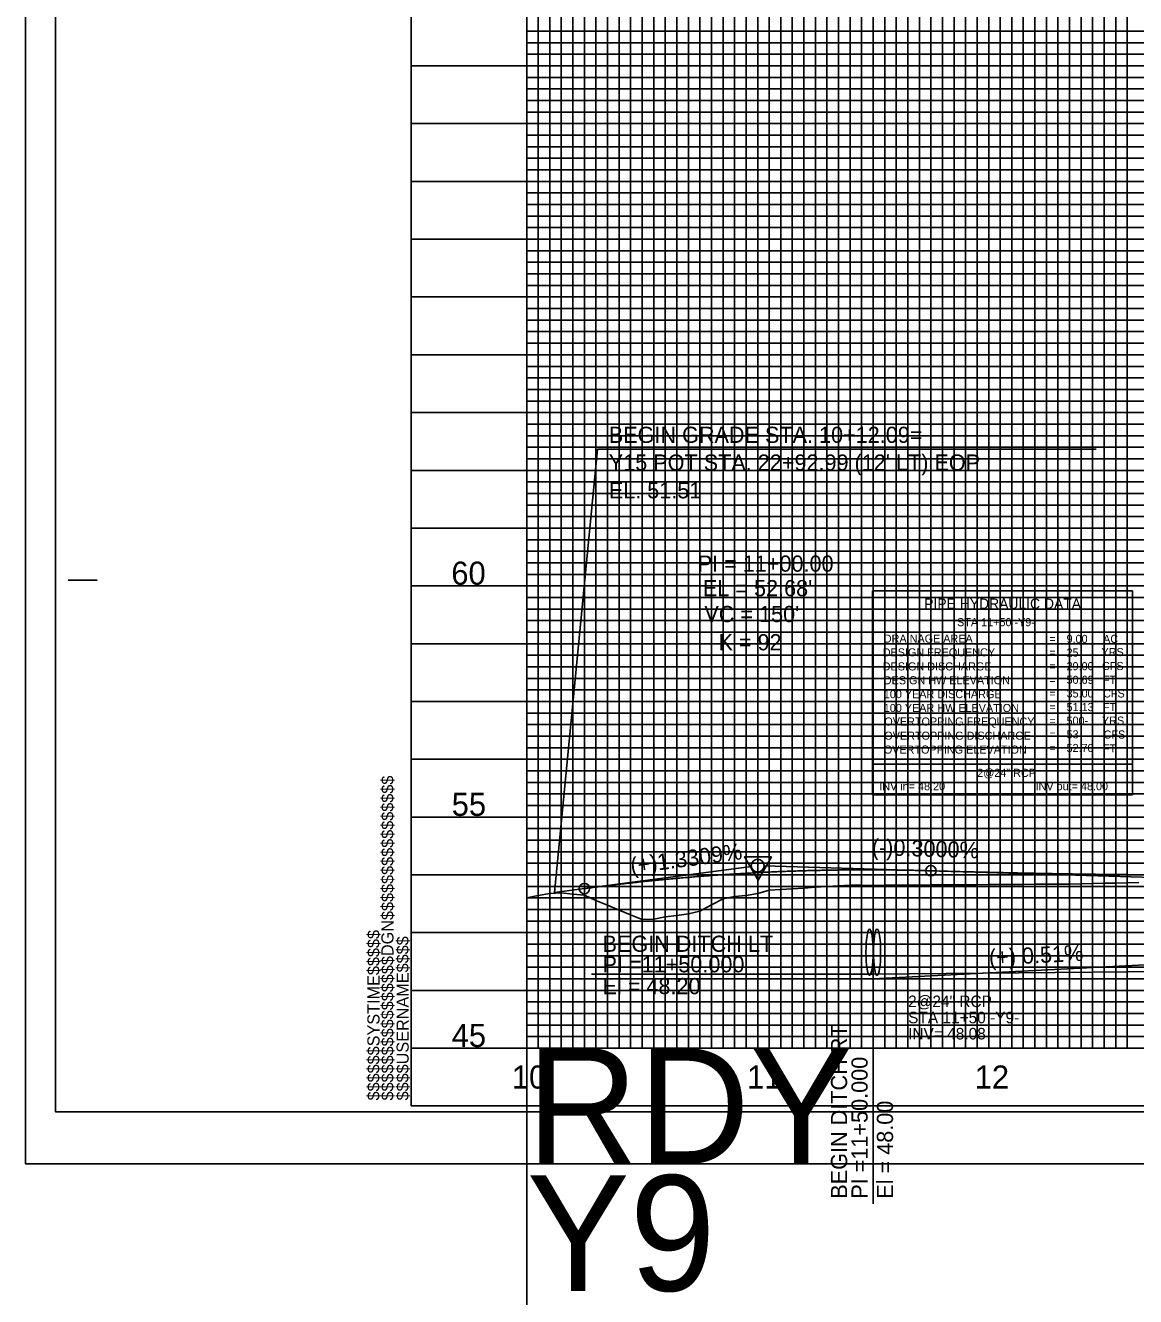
# Model space of a CAD drawing. Extents: x 2345490 to 2436403, y 465165 to 573888.
# Drawn here: x 2381463 to 2381944, y 536093 to 536643 of the extents above; entities that cross this region are included whole.
import ezdxf

# ---------------------------------------------------------------- set-up
doc = ezdxf.new("R2010")
doc.units = 0
for name, color, linetype in [('Old_Level_1', 7, 'Continuous'), ('Old_Level_18', 7, 'Continuous'), ('Old_Level_2', 7, 'Continuous'), ('Old_Level_3', 7, 'Continuous'), ('Old_Level_4', 7, 'Continuous'), ('Old_Level_40', 7, 'Continuous'), ('Old_Level_41', 7, 'Continuous'), ('Old_Level_42', 7, 'Continuous'), ('Old_Level_43', 7, 'Continuous'), ('Old_Level_50', 7, 'Continuous'), ('Old_Level_51', 7, 'Continuous'), ('Old_Level_52', 7, 'Continuous'), ('Old_Level_57', 7, 'Continuous'), ('Old_Level_62', 7, 'Continuous'), ('Old_Level_63', 7, 'Continuous')]:
    doc.layers.add(name, color=color, linetype=linetype)

msp = doc.modelspace()

# ---------------------------------------------------------------- linework, layer by layer
at = {"layer": 'Old_Level_1'}
msp.add_lwpolyline([(2381680.454, 536265.78575), (2381685.454, 536266.76675), (2381690.454, 536267.5915), (2381695.454, 536267.94525), (2381700.454, 536267.37375), (2381705.454, 536266.8275), (2381710.454, 536264.5385), (2381715.454, 536262.4825), (2381720.454, 536260.4265), (2381725.454, 536258.37075), (2381730.454, 536256.31475), (2381735.454, 536256.54975), (2381740.454, 536257.4375), (2381745.454, 536258.12375), (2381750.454, 536258.81025), (2381755.454, 536259.99975), (2381760.454, 536262.64725), (2381765.454, 536265.302), (2381770.454, 536266.2445), (2381775.454, 536266.77975), (2381780.454, 536267.62925), (2381785.454, 536269.07675), (2381790.454, 536269.3925), (2381795.454, 536269.613), (2381800.454, 536269.93925), (2381805.454, 536270.26575), (2381810.454, 536270.59225), (2381815.454, 536270.9185), (2381820.454, 536271.22525), (2381825.454, 536271.18625), (2381830.454, 536271.10175), (2381835.454, 536271.13775), (2381840.454, 536271.1735), (2381845.454, 536271.2095), (2381850.454, 536271.2455), (2381855.454, 536271.283), (2381860.454, 536271.28275), (2381865.454, 536271.3205), (2381870.454, 536271.35825), (2381875.454, 536271.396), (2381880.454, 536271.4335), (2381885.454, 536271.47225), (2381890.454, 536271.51025), (2381895.454, 536271.54775), (2381900.454, 536271.5855), (2381905.454, 536271.62325), (2381910.454, 536271.66075), (2381915.454, 536271.6995), (2381920.454, 536271.822), (2381925.454, 536271.92225), (2381930.454, 536272.02225), (2381935.454, 536272.12225), (2381940.454, 536272.2225), (2381945.454, 536272.3225)], dxfattribs=at)
at = {"layer": 'Old_Level_18'}
msp.add_line((2381630.454, 536175.68175), (2381630.454, 536175.68175), dxfattribs=at)
msp.add_line((2381630.454, 536175.68175), (2381630.454, 536175.68175), dxfattribs=at)
msp.add_lwpolyline([(2383130.454, 537225.68175), (2381630.454, 537225.68175), (2381630.454, 536175.68175), (2383130.454, 536175.68175)], close=True, dxfattribs=at)
at = {"layer": 'Old_Level_2'}
for p, q in [((2381692.544, 536267.98175), (2381711.1685, 536459.8775)), ((2381711.1685, 536459.8775), (2381927.03675, 536459.8775)), ((2381705.454, 536269.69975), (2381777.72825, 536279.31875)), ((2381855.454, 536277.43175), (2381783.203, 536279.59925)), ((2381855.454, 536277.43175), (2381977.70525, 536273.764)), ((2381692.544, 536267.98175), (2381705.454, 536269.69975))]:
    msp.add_line(p, q, dxfattribs=at)
msp.add_lwpolyline([(2381786.4715, 536283.452), (2381774.729, 536283.4375), (2381780.6125, 536273.31925)], close=True, dxfattribs=at)
for centre, radius in [((2381780.454, 536279.68175), 2.75), ((2381855.454, 536277.43175), 2.25), ((2381705.454, 536269.69975), 2.25)]:
    msp.add_circle(centre, radius, dxfattribs=at)
for points in [[(2381705.454, 536269.69975), (2381708.454, 536270.09425), (2381711.454, 536270.47875), (2381714.454, 536270.8535), (2381717.454, 536271.21875), (2381720.454, 536271.57375), (2381723.454, 536271.91925), (2381726.454, 536272.255), (2381729.454, 536272.58075), (2381732.454, 536272.897), (2381735.454, 536273.20325), (2381738.454, 536273.49975), (2381741.454, 536273.7865), (2381744.454, 536274.0635), (2381747.454, 536274.33075), (2381750.454, 536274.588), (2381753.454, 536274.83575), (2381756.454, 536275.0735), (2381759.454, 536275.3015), (2381762.454, 536275.51975), (2381765.454, 536275.72825), (2381768.454, 536275.92675), (2381771.454, 536276.11575), (2381774.454, 536276.29475), (2381777.454, 536276.46425), (2381780.454, 536276.62375), (2381783.454, 536276.7735), (2381786.454, 536276.9135), (2381789.454, 536277.0435), (2381792.454, 536277.164), (2381795.454, 536277.2745), (2381798.454, 536277.37525), (2381801.454, 536277.4665), (2381804.454, 536277.54775), (2381807.454, 536277.619), (2381810.454, 536277.68075), (2381813.454, 536277.73275), (2381816.454, 536277.77475), (2381819.454, 536277.807), (2381822.454, 536277.8295), (2381825.454, 536277.84225), (2381828.454, 536277.84525), (2381831.454, 536277.8385), (2381834.454, 536277.822), (2381837.454, 536277.7955), (2381840.454, 536277.75925), (2381843.454, 536277.71325), (2381846.454, 536277.6575), (2381849.454, 536277.592), (2381852.454, 536277.51675), (2381855.454, 536277.43175)], [(2381855.454, 536277.43175), (2381860.454, 536277.28475), (2381865.454, 536277.14375), (2381870.454, 536277.00875), (2381875.454, 536276.87975), (2381880.454, 536276.75675), (2381885.454, 536276.63975), (2381890.454, 536276.52875), (2381895.454, 536276.42375), (2381900.454, 536276.32475), (2381905.454, 536276.23175), (2381910.454, 536276.14475), (2381915.454, 536276.06375), (2381920.454, 536275.98875), (2381925.454, 536275.91975), (2381930.454, 536275.85675), (2381935.454, 536275.79975), (2381940.454, 536275.74875), (2381945.454, 536275.70375), (2381950.454, 536275.66475), (2381955.454, 536275.63175), (2381960.454, 536275.60475), (2381965.454, 536275.58375), (2381970.454, 536275.56875), (2381975.454, 536275.55975), (2381980.454, 536275.55675), (2381985.454, 536275.55975), (2381990.454, 536275.56875), (2381995.454, 536275.58375), (2382000.454, 536275.60475), (2382005.454, 536275.63175), (2382010.454, 536275.66475), (2382015.454, 536275.70375), (2382020.454, 536275.74875), (2382025.454, 536275.79975), (2382030.454, 536275.85675), (2382035.454, 536275.91975), (2382040.454, 536275.98875), (2382045.454, 536276.06375), (2382050.454, 536276.14475), (2382055.454, 536276.23175), (2382060.454, 536276.32475), (2382065.454, 536276.42375), (2382070.454, 536276.52875), (2382075.454, 536276.63975), (2382080.454, 536276.75675), (2382085.454, 536276.87975), (2382090.454, 536277.00875), (2382095.454, 536277.14375), (2382100.454, 536277.28475), (2382105.454, 536277.43175)]]:
    msp.add_spline(points, degree=3, dxfattribs=at)
at = {"layer": 'Old_Level_3'}
for p, q in [((2381830.454, 536230.68175), (2381980.454, 536238.38175)), ((2381830.454, 536232.68175), (2382170.454, 536235.88175)), ((2381708.48161, 536232.68175), (2381830.454, 536232.68175)), ((2381830.454, 536230.68175), (2381830.454, 536133.33096))]:
    msp.add_line(p, q, dxfattribs=at)
for centre in [(2381828.89623, 536242.16343), (2381832.1238, 536242.16345)]:
    msp.add_ellipse(centre, major_axis=(0, 10), ratio=0.156140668, dxfattribs=at)
at = {"layer": 'Old_Level_4'}
for p, q in [((2381830.15461, 536398.55967), (2381942.65461, 536398.55967)), ((2381830.15461, 536323.55967), (2381830.15461, 536398.55967)), ((2381942.65461, 536398.55967), (2381942.65461, 536323.55967)), ((2381942.65461, 536323.55967), (2381830.15461, 536323.55967))]:
    msp.add_line(p, q, dxfattribs=at)
msp.add_lwpolyline([(2381830.15461, 536323.55967), (2381942.65461, 536323.55967), (2381942.65461, 536310.34467), (2381830.15461, 536310.34467)], close=True, dxfattribs=at)
at = {"layer": 'Old_Level_40'}
msp.add_line((2381630.454, 536175.68175), (2381630.454, 536175.68175), dxfattribs=at)
msp.add_line((2381630.454, 536175.68175), (2381630.454, 536175.68175), dxfattribs=at)
msp.add_line((2381630.454, 536175.68175), (2381630.454, 536175.68175), dxfattribs=at)
msp.add_line((2381630.454, 536175.68175), (2381630.454, 536175.68175), dxfattribs=at)
at = {"layer": 'Old_Level_41'}
for p, q in [((2381481.954, 536403.18175), (2381494.454, 536403.18175)), ((2383130.454, 536200.68175), (2381630.454, 536200.68175))]:
    msp.add_line(p, q, dxfattribs=at)
for points in [[(2381630.454, 537225.68175), (2381680.454, 537225.68175), (2381680.454, 536200.68175), (2381730.454, 536200.68175), (2381730.454, 537225.68175), (2381780.454, 537225.68175), (2381780.454, 536200.68175), (2381830.454, 536200.68175), (2381830.454, 537225.68175), (2381880.454, 537225.68175), (2381880.454, 536200.68175), (2381930.454, 536200.68175), (2381930.454, 537225.68175), (2381980.454, 537225.68175), (2381980.454, 536200.68175), (2382030.454, 536200.68175), (2382030.454, 537225.68175), (2382080.454, 537225.68175), (2382080.454, 536200.68175), (2382130.454, 536200.68175), (2382130.454, 537225.68175), (2382180.454, 537225.68175), (2382180.454, 536200.68175), (2382230.454, 536200.68175)], [(2381705.454, 536200.68175), (2381705.454, 537225.68175), (2381755.454, 537225.68175), (2381755.454, 536200.68175), (2381805.454, 536200.68175), (2381805.454, 537225.68175), (2381855.454, 537225.68175), (2381855.454, 536200.68175), (2381905.454, 536200.68175), (2381905.454, 537225.68175), (2381955.454, 537225.68175), (2381955.454, 536200.68175), (2382005.454, 536200.68175), (2382005.454, 537225.68175), (2382055.454, 537225.68175), (2382055.454, 536200.68175), (2382105.454, 536200.68175), (2382105.454, 537225.68175), (2382155.454, 537225.68175), (2382155.454, 536200.68175), (2382205.454, 536200.68175)], [(2383130.454, 536625.68175), (2381630.454, 536625.68175), (2381630.454, 536575.68175), (2383130.454, 536575.68175)], [(2383130.454, 536550.68175), (2381630.454, 536550.68175), (2381630.454, 536600.68175), (2383130.454, 536600.68175)], [(2383130.454, 536525.68175), (2381630.454, 536525.68175), (2381630.454, 536475.68175), (2383130.454, 536475.68175)], [(2383130.454, 536450.68175), (2381630.454, 536450.68175), (2381630.454, 536500.68175), (2383130.454, 536500.68175)], [(2383130.454, 536425.68175), (2381630.454, 536425.68175), (2381630.454, 536375.68175), (2383130.454, 536375.68175)], [(2383130.454, 536325.68175), (2381630.454, 536325.68175), (2381630.454, 536275.68175), (2383130.454, 536275.68175)], [(2383130.454, 536250.68175), (2381630.454, 536250.68175), (2381630.454, 536300.68175), (2383130.454, 536300.68175)], [(2383130.454, 536225.68175), (2381630.454, 536225.68175)], [(2381667.954, 536175.68175), (2381667.954, 536175.68175)]]:
    msp.add_lwpolyline(points, dxfattribs=at)
at = {"layer": 'Old_Level_42'}
msp.add_lwpolyline([(2383130.454, 536350.68175), (2381630.454, 536350.68175), (2381630.454, 536400.68175), (2383130.454, 536400.68175)], dxfattribs=at)
at = {"layer": 'Old_Level_43'}
for points in [[(2381685.454, 537225.68175), (2381685.454, 536200.68175), (2381690.454, 536200.68175), (2381690.454, 537225.68175)], [(2381695.454, 537225.68175), (2381695.454, 536200.68175), (2381700.454, 536200.68175), (2381700.454, 537225.68175)], [(2381710.454, 537225.68175), (2381710.454, 536200.68175), (2381715.454, 536200.68175), (2381715.454, 537225.68175)], [(2381720.454, 537225.68175), (2381720.454, 536200.68175), (2381725.454, 536200.68175), (2381725.454, 537225.68175)], [(2381735.454, 537225.68175), (2381735.454, 536200.68175), (2381740.454, 536200.68175), (2381740.454, 537225.68175)], [(2381745.454, 537225.68175), (2381745.454, 536200.68175), (2381750.454, 536200.68175), (2381750.454, 537225.68175)], [(2381760.454, 537225.68175), (2381760.454, 536200.68175), (2381765.454, 536200.68175), (2381765.454, 537225.68175)], [(2381770.454, 537225.68175), (2381770.454, 536200.68175), (2381775.454, 536200.68175), (2381775.454, 537225.68175)], [(2381785.454, 537225.68175), (2381785.454, 536200.68175), (2381790.454, 536200.68175), (2381790.454, 537225.68175)], [(2381795.454, 537225.68175), (2381795.454, 536200.68175), (2381800.454, 536200.68175), (2381800.454, 537225.68175)], [(2381810.454, 537225.68175), (2381810.454, 536200.68175), (2381815.454, 536200.68175), (2381815.454, 537225.68175)], [(2381820.454, 537225.68175), (2381820.454, 536200.68175), (2381825.454, 536200.68175), (2381825.454, 537225.68175)], [(2381835.454, 537225.68175), (2381835.454, 536200.68175), (2381840.454, 536200.68175), (2381840.454, 537225.68175)], [(2381845.454, 536200.68175), (2381850.454, 536200.68175), (2381850.454, 537225.68175)], [(2381845.454, 537225.68175), (2381845.454, 536200.68175)], [(2381860.454, 537225.68175), (2381860.454, 536200.68175), (2381865.454, 536200.68175), (2381865.454, 537225.68175)], [(2381870.454, 537225.68175), (2381870.454, 536200.68175), (2381875.454, 536200.68175), (2381875.454, 537225.68175)], [(2381885.454, 537225.68175), (2381885.454, 536200.68175), (2381890.454, 536200.68175), (2381890.454, 537225.68175)], [(2381895.454, 537225.68175), (2381895.454, 536200.68175), (2381900.454, 536200.68175), (2381900.454, 537225.68175)], [(2381910.454, 537225.68175), (2381910.454, 536200.68175), (2381915.454, 536200.68175), (2381915.454, 537225.68175)], [(2381920.454, 537225.68175), (2381920.454, 536200.68175), (2381925.454, 536200.68175), (2381925.454, 537225.68175)], [(2381935.454, 537225.68175), (2381935.454, 536200.68175), (2381940.454, 536200.68175), (2381940.454, 537225.68175)], [(2383080.454, 536640.68175), (2381680.454, 536640.68175), (2381680.454, 536635.68175), (2383080.454, 536635.68175)], [(2383080.454, 536630.68175), (2381680.454, 536630.68175), (2381680.454, 536620.68175), (2383080.454, 536620.68175)], [(2383080.454, 536615.68175), (2381680.454, 536615.68175), (2381680.454, 536610.68175), (2383080.454, 536610.68175)], [(2383080.454, 536605.68175), (2381680.454, 536605.68175), (2381680.454, 536595.68175), (2383080.454, 536595.68175)], [(2383080.454, 536590.68175), (2381680.454, 536590.68175), (2381680.454, 536585.68175), (2383080.454, 536585.68175)], [(2383080.454, 536580.68175), (2381680.454, 536580.68175), (2381680.454, 536570.68175), (2383080.454, 536570.68175)], [(2383080.454, 536565.68175), (2381680.454, 536565.68175), (2381680.454, 536560.68175), (2383080.454, 536560.68175)], [(2383080.454, 536555.68175), (2381680.454, 536555.68175), (2381680.454, 536545.68175), (2383080.454, 536545.68175)], [(2383080.454, 536540.68175), (2381680.454, 536540.68175), (2381680.454, 536535.68175), (2383080.454, 536535.68175)], [(2383080.454, 536530.68175), (2381680.454, 536530.68175), (2381680.454, 536520.68175), (2383080.454, 536520.68175)], [(2383080.454, 536515.68175), (2381680.454, 536515.68175), (2381680.454, 536510.68175), (2383080.454, 536510.68175)], [(2383080.454, 536505.68175), (2381680.454, 536505.68175), (2381680.454, 536495.68175), (2383080.454, 536495.68175)], [(2383080.454, 536490.68175), (2381680.454, 536490.68175), (2381680.454, 536485.68175), (2383080.454, 536485.68175)], [(2383080.454, 536480.68175), (2381680.454, 536480.68175), (2381680.454, 536470.68175), (2383080.454, 536470.68175)], [(2383080.454, 536465.68175), (2381680.454, 536465.68175), (2381680.454, 536460.68175), (2383080.454, 536460.68175)], [(2383080.454, 536455.68175), (2381680.454, 536455.68175), (2381680.454, 536445.68175), (2383080.454, 536445.68175)], [(2383080.454, 536440.68175), (2381680.454, 536440.68175), (2381680.454, 536435.68175), (2383080.454, 536435.68175)], [(2383080.454, 536430.68175), (2381680.454, 536430.68175), (2381680.454, 536420.68175), (2383080.454, 536420.68175)], [(2383080.454, 536415.68175), (2381680.454, 536415.68175), (2381680.454, 536410.68175), (2383080.454, 536410.68175)], [(2383080.454, 536405.68175), (2381680.454, 536405.68175)], [(2381680.454, 536395.68175), (2383080.454, 536395.68175)], [(2383080.454, 536390.68175), (2381680.454, 536390.68175), (2381680.454, 536385.68175), (2383080.454, 536385.68175)], [(2383080.454, 536380.68175), (2381680.454, 536380.68175)], [(2381680.454, 536370.68175), (2383080.454, 536370.68175)], [(2383080.454, 536365.68175), (2381680.454, 536365.68175), (2381680.454, 536360.68175), (2383080.454, 536360.68175)], [(2383080.454, 536355.68175), (2381680.454, 536355.68175), (2381680.454, 536345.68175), (2383080.454, 536345.68175)], [(2383080.454, 536340.68175), (2381680.454, 536340.68175), (2381680.454, 536335.68175), (2383080.454, 536335.68175)], [(2383080.454, 536330.68175), (2381680.454, 536330.68175), (2381680.454, 536320.68175), (2383080.454, 536320.68175)], [(2383080.454, 536315.68175), (2381680.454, 536315.68175), (2381680.454, 536310.68175), (2383080.454, 536310.68175)], [(2383080.454, 536305.68175), (2381680.454, 536305.68175), (2381680.454, 536295.68175), (2383080.454, 536295.68175)], [(2383080.454, 536290.68175), (2381680.454, 536290.68175), (2381680.454, 536285.68175), (2383080.454, 536285.68175)], [(2383080.454, 536280.68175), (2381680.454, 536280.68175), (2381680.454, 536270.68175), (2383080.454, 536270.68175)], [(2383080.454, 536265.68175), (2381680.454, 536265.68175), (2381680.454, 536260.68175), (2383080.454, 536260.68175)], [(2383080.454, 536255.68175), (2381680.454, 536255.68175), (2381680.454, 536245.68175), (2383080.454, 536245.68175)], [(2383080.454, 536240.68175), (2381680.454, 536240.68175), (2381680.454, 536235.68175), (2383080.454, 536235.68175)], [(2383080.454, 536230.68175), (2381680.454, 536230.68175), (2381680.454, 536220.68175), (2383080.454, 536220.68175)], [(2383080.454, 536215.68175), (2381680.454, 536215.68175), (2381680.454, 536210.68175), (2383080.454, 536210.68175)], [(2383080.454, 536205.68175), (2381680.454, 536205.68175)]]:
    msp.add_lwpolyline(points, dxfattribs=at)
at = {"layer": 'Old_Level_50'}
msp.add_line((2381463.454, 536150.68175), (2381463.454, 536150.68175), dxfattribs=at)
msp.add_lwpolyline([(2383142.954, 537228.23175), (2381476.454, 537228.23175), (2381476.454, 536173.13175), (2383142.954, 536173.13175)], close=True, dxfattribs=at)
at = {"layer": 'Old_Level_51'}
msp.add_lwpolyline([(2383147.454, 537250.68175), (2381463.454, 537250.68175), (2381463.454, 536150.68175), (2383147.454, 536150.68175)], close=True, dxfattribs=at)
at = {"layer": 'Old_Level_52'}
msp.add_line((2381476.454, 536173.13175), (2381476.454, 536173.13175), dxfattribs=at)
at = {"layer": 'Old_Level_57'}
for p, q in [((2381630.45425, 536450.682), (2383880.45375, 536450.682)), ((2381680.45375, 536200.682), (2381680.45375, 536450.682)), ((2381780.45375, 536200.682), (2381780.45375, 536450.682)), ((2381880.45375, 536200.682), (2381880.45375, 536450.682)), ((2381630.45425, 536400.682), (2383880.45375, 536400.682)), ((2381630.45425, 536350.682), (2383880.45375, 536350.682)), ((2381630.45425, 536300.682), (2383880.45375, 536300.682)), ((2381630.454, 536250.682), (2383880.45375, 536250.682)), ((2381630.45425, 536200.682), (2383880.45375, 536200.682))]:
    msp.add_line(p, q, dxfattribs=at)
at = {"layer": 'Old_Level_63'}
for q in [(2381680.454, 538700.68175), (2383096.698, 536200.68175), (2381680.454, 533700.68175)]:
    msp.add_line((2381680.454, 536200.68175), q, dxfattribs=at)

# ---------------------------------------------------------------- texts
at = {"layer": 'Old_Level_2'}
for s, height, p in [('BEGIN GRADE STA. 10+12.09=', 7.0000005, (2381715.995, 536462.55925)), ("Y15 POT STA. 22+92.99 (12' LT) EOP", 7.0000005, (2381715.995, 536450.55925)), ('EL. 51.51', 7.000001, (2381715.995, 536438.55925)), ('PI = 11+00.00', 7.0000005, (2381754.4915, 536406.83525)), ("EL = 52.68'", 7.0000005, (2381756.76275, 536396.21)), ("VC = 150'", 7.000001, (2381757.3835, 536385.01325)), ('K = 92', 7.000001, (2381763.482, 536372.81075))]:
    msp.add_text(s, height=height, dxfattribs=at).set_placement(p)
for s, rotation, p in [('(+)1.3309%', 7.5809806, (2381725.83821, 536276.04694)), ('(-)0.3000%', 358.2816417, (2381829.76791, 536284.21853))]:
    msp.add_text(s, height=7.000001, rotation=rotation, dxfattribs=at).set_placement(p)
at = {"layer": 'Old_Level_3'}
for s, height, p in [('BEGIN DITCH LT', 7.0000005, (2381713.29835, 536242.35528)), ('PI =11+50.000', 7.0000005, (2381713.29835, 536233.48138)), ('El = 48.20', 7.000001, (2381713.29835, 536224.02985)), ('2@24" RCP', 5, (2381845.566, 536218.4425)), ('STA 11+50 -Y9-', 4.9999995, (2381845.566, 536211.4425)), ('INV= 48.08', 5, (2381845.566, 536204.4425))]:
    msp.add_text(s, height=height, dxfattribs=at).set_placement(p)
for s, height, rotation, p in [('(+) 0.51%', 7, 2.9386028, (2381880.75045, 536236.39092)), ('BEGIN DITCH RT', 7.0000005, 90, (2381819.1751, 536135.542)), ('PI =11+50.000', 7.0000005, 90, (2381828.049, 536135.542)), ('El = 48.00', 7.000001, 90, (2381839.049, 536135.542))]:
    msp.add_text(s, height=height, rotation=rotation, dxfattribs=at).set_placement(p)
at = {"layer": 'Old_Level_4'}
for s, height, p in [('PIPE HYDRAULIC DATA', 4.49985, (2381852.55461, 536390.73467)), ('STA 11+50 -Y9-', 3.4998, (2381866.77536, 536383.23417)), ('DRAINAGE AREA', 3.49995, (2381835.05461, 536376.10967)), ('=        ', 3.49995, (2381906.70461, 536376.00967)), ('9.00', 3.49995, (2381914.16511, 536376.00917)), ('AC', 3.49995, (2381929.97961, 536376.00967)), ('DESIGN FREQUENCY', 3.49995, (2381834.60461, 536370.18467)), ('=        ', 3.49995, (2381906.70461, 536370.10967)), ('25', 3.49995, (2381914.16511, 536370.10942)), ('YRS', 3.49995, (2381929.27961, 536370.30967)), ('DESIGN DISCHARGE', 3.49995, (2381834.60461, 536364.10967)), ('=        ', 3.49995, (2381906.70461, 536364.20967)), ('29.00', 3.49995, (2381914.16511, 536364.20942)), ('CFS', 3.49995, (2381929.50461, 536364.28467)), ('DESIGN HW ELEVATION', 3.49995, (2381835.05461, 536358.10967)), ('=        ', 3.49995, (2381906.70461, 536358.30967)), ('50.69', 3.49995, (2381914.16511, 536358.30942)), ('FT', 3.49995, (2381929.97961, 536358.30967)), ('100 YEAR DISCHARGE', 3.49995, (2381835.05461, 536352.10967)), ('=        ', 3.49995, (2381906.70461, 536352.40967)), ('35.00', 3.49995, (2381914.16511, 536352.40942)), ('CFS', 3.49995, (2381929.97961, 536352.40967)), ('100 YEAR HW ELEVATION', 3.49995, (2381835.05461, 536346.10967)), ('=        ', 3.49995, (2381906.70461, 536346.50967)), ('51.13', 3.49995, (2381914.16511, 536346.50942)), ('FT', 3.49995, (2381929.97961, 536346.50967)), ('OVERTOPPING FREQUENCY', 3.49995, (2381835.27961, 536340.25967)), ('=        ', 3.49995, (2381906.70461, 536340.60967)), ('500-', 3.49995, (2381914.16511, 536340.60967)), ('YRS', 3.49995, (2381929.50461, 536340.65967)), ('OVERTOPPING DISCHARGE', 3.49995, (2381835.27961, 536334.13467)), ('=        ', 3.49995, (2381906.70461, 536334.70967)), ('53', 3.49995, (2381914.16511, 536334.70967)), ('CFS', 3.49995, (2381930.20461, 536334.63467)), ('52.70', 3.49995, (2381914.16511, 536328.80967)), ('FT', 3.49995, (2381929.97961, 536328.60967)), ('OVERTOPPING ELEVATION', 3.49995, (2381835.05461, 536328.10967)), ('=        ', 3.49995, (2381906.70461, 536328.80967)), ('2@24" RCP', 3.4998, (2381875.54386, 536318.06242)), ('INV in= 48.20', 3.4998, (2381833.08711, 536312.27167)), ('INV out= 48.00', 3.4998, (2381900.76386, 536312.27167))]:
    msp.add_text(s, height=height, dxfattribs=at).set_placement(p)
at = {"layer": 'Old_Level_41'}
for s, p in [('$$$$$$$$$$$$$$$$DGN$$$$$$$$$$$$$$$$', (2381622.804, 536178.04425)), ('$$$$$$SYSTIME$$$$$', (2381616.754, 536178.04425)), ('$$$$USERNAME$$$$', (2381629.379, 536178.05675))]:
    msp.add_text(s, height=5.25, rotation=90, dxfattribs=at).set_placement(p)
at = {"layer": 'Old_Level_62'}
for s, p in [('60', (2381647.8405, 536401.18175)), ('55', (2381647.998, 536301.18175)), ('45', (2381647.998, 536201.18175)), ('10', (2381674.0375, 536183.18175)), ('11', (2381775.877, 536183.18175)), ('12', (2381874.42525, 536183.18175))]:
    msp.add_text(s, height=10.000001, dxfattribs=at).set_placement(p)
at = {"layer": 'Old_Level_63'}
for s, p in [('RDY', (2381680.454, 536150.68175)), ('Y9', (2381680.454, 536095.68175))]:
    msp.add_text(s, height=50, dxfattribs=at).set_placement(p)

doc.saveas('drawing.dxf')
